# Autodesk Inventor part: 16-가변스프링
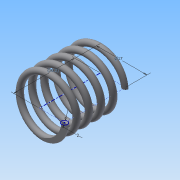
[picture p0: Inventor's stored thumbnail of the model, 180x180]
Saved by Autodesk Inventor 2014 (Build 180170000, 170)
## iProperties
Created: 2016-01
Part Number: 16-가변스프링
Material: Generic
Document SubType Name: Modeling
Designer: Administrator
Density: 1 g/cm^3
Appearance: Default
Author: Administrator
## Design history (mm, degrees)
sketch "스케치1"
  geometry: L1 (0, 0)-(8.5, 0); L2 (8.5, 0)-(8.5, 20.5); L3 (8.5, 20.5)-(0, 20.5); L4 (0, 20.5)-(0, 0); C1 r 1 at (8.5, 0)
  constraints: 8 end point, 2 parallel, 1 centre point, 1 coincident, 1 horizontal, 1 perpendicular
  dimensions: "d0" = 20.5 distance of L3.end L1.start (derived); "d1" = 17 diameter of L2 L4; "d2" = 2 diameter of C1
feature "코일1" pitch "d3" = 10; turns "d5" = 5; dims "d4" = 20.5 (= d0), "d6" = 0, angle "d7" = 90 deg, angle "d8" = 90 deg, "d9" = 0, "d10" = 0
node "작업 평면1"
sketch "스케치2"
  geometry: L1 (7.5, 0)-(9.5, 0) reference; 1 further point
  constraints: 1 horizontal alignment
extrude "돌출1" cut sketch "스케치2" stored distance "d12" = 10; taper "d13" = 0 deg
node "작업 평면2"
sketch "스케치3"
  geometry: L1 (-7.5, 0)-(-9.5, 0) reference; 1 further point
  constraints: 1 horizontal alignment
extrude "돌출2" cut sketch "스케치3" stored distance "d15" = 10; taper "d16" = 0 deg
node "솔리드1"
node "절단 모서리 투영1"
node "절단 모서리 투영2"
other parameters: "d11" = 0, "d14" = 20.5 (= d0)
